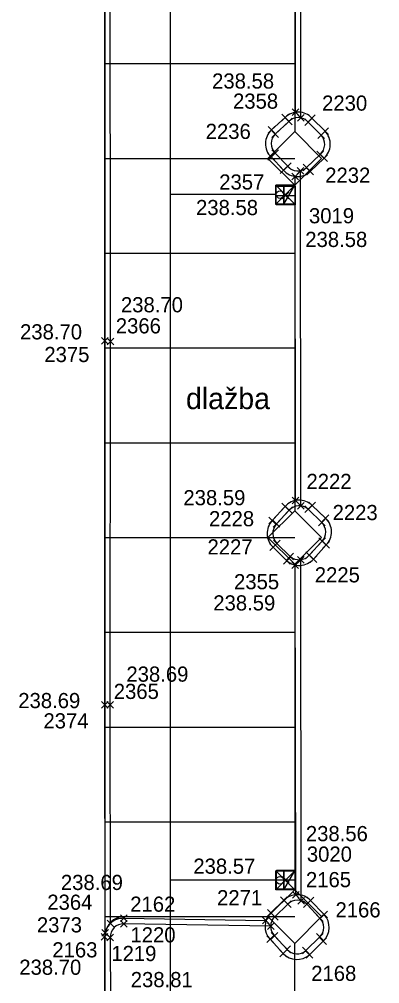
# Model space of a CAD drawing. Extents: x -264222 to -263676, y -1242344 to -1242060.
# Drawn here: x -264127.84 to -264118.33, y -1242272.25 to -1242246.81 of the extents above; entities that cross this region are included whole.
import ezdxf

# ---------------------------------------------------------------- set-up
doc = ezdxf.new("R2010")
doc.units = 0
for name, color, linetype in [('BODY_CISLO', 7, 'Continuous'), ('BODY_SYMBOL', 7, 'Continuous'), ('BODY_VYSKA', 7, 'Continuous'), ('BODY_VYSKY_UV', 7, 'Continuous'), ('KOORDINACNA_SITUACIA_DSP', 7, 'Continuous'), ('POPIS', 7, 'Continuous'), ('PROJEKT_DRS_OBRUBNIKY_KOMUNIKACIE', 7, 'Continuous'), ('PROJEKT_DRS_TDZ_VODOROVNE', 7, 'Continuous'), ('PROJEKT_DRS_UV_STAVBY', 7, 'Continuous'), ('SO_20-3_OBRUBNIKY_DOLNA_HRANA', 7, 'Continuous'), ('SO_20-3_OBRUBNIKY_HORNA_HRANA', 7, 'Continuous'), ('ULICNA_VPUST_POKLOP', 7, 'Continuous')]:
    doc.layers.add(name, color=color, linetype=linetype)

msp = doc.modelspace()

# ---------------------------------------------------------------- linework, layer by layer
at = {"layer": 'BODY_SYMBOL'}
for p, q in [((-264120.638, -1242249.353), (-264120.462, -1242249.177)), ((-264120.462, -1242249.353), (-264120.638, -1242249.177)), ((-264120.912, -1242249.488), (-264120.736, -1242249.312)), ((-264120.736, -1242249.488), (-264120.912, -1242249.312)), ((-264120.813, -1242249.596), (-264120.637, -1242249.42)), ((-264120.637, -1242249.596), (-264120.813, -1242249.42)), ((-264120.493, -1242249.503), (-264120.317, -1242249.327)), ((-264120.317, -1242249.503), (-264120.493, -1242249.327)), ((-264120.302, -1242249.612), (-264120.126, -1242249.436)), ((-264120.126, -1242249.612), (-264120.302, -1242249.436)), ((-264120.203, -1242249.506), (-264120.027, -1242249.33)), ((-264120.027, -1242249.506), (-264120.203, -1242249.33)), ((-264121.27, -1242249.82), (-264121.094, -1242249.644)), ((-264121.094, -1242249.82), (-264121.27, -1242249.644)), ((-264119.858, -1242249.853), (-264119.682, -1242249.677)), ((-264119.682, -1242249.853), (-264119.858, -1242249.677)), ((-264121.17, -1242249.928), (-264120.994, -1242249.752)), ((-264120.994, -1242249.928), (-264121.17, -1242249.752)), ((-264119.961, -1242249.957), (-264119.785, -1242249.781)), ((-264119.785, -1242249.957), (-264119.961, -1242249.781)), ((-264121.282, -1242250.533), (-264121.106, -1242250.357)), ((-264121.106, -1242250.533), (-264121.282, -1242250.357)), ((-264121.174, -1242250.429), (-264120.998, -1242250.253)), ((-264120.998, -1242250.429), (-264121.174, -1242250.253)), ((-264119.987, -1242250.466), (-264119.811, -1242250.29)), ((-264119.811, -1242250.466), (-264119.987, -1242250.29)), ((-264119.884, -1242250.568), (-264119.708, -1242250.392)), ((-264119.708, -1242250.568), (-264119.884, -1242250.392)), ((-264120.952, -1242250.884), (-264120.776, -1242250.708)), ((-264120.776, -1242250.884), (-264120.952, -1242250.708)), ((-264120.843, -1242250.78), (-264120.667, -1242250.604)), ((-264120.667, -1242250.78), (-264120.843, -1242250.604)), ((-264120.508, -1242250.896), (-264120.332, -1242250.72)), ((-264120.332, -1242250.896), (-264120.508, -1242250.72)), ((-264120.346, -1242250.812), (-264120.17, -1242250.636)), ((-264120.17, -1242250.812), (-264120.346, -1242250.636)), ((-264120.249, -1242250.917), (-264120.073, -1242250.741)), ((-264120.073, -1242250.917), (-264120.249, -1242250.741)), ((-264120.648, -1242251.045), (-264120.472, -1242250.869)), ((-264120.472, -1242251.045), (-264120.648, -1242250.869)), ((-264120.898, -1242251.549), (-264120.722, -1242251.373)), ((-264120.722, -1242251.549), (-264120.898, -1242251.373)), ((-264125.663, -1242255.387), (-264125.487, -1242255.211)), ((-264125.487, -1242255.387), (-264125.663, -1242255.211)), ((-264125.519, -1242255.403), (-264125.343, -1242255.227)), ((-264125.343, -1242255.403), (-264125.519, -1242255.227)), ((-264120.909, -1242259.752), (-264120.733, -1242259.576)), ((-264120.733, -1242259.752), (-264120.909, -1242259.576)), ((-264120.636, -1242259.595), (-264120.46, -1242259.419)), ((-264120.46, -1242259.595), (-264120.636, -1242259.419)), ((-264120.493, -1242259.737), (-264120.317, -1242259.561)), ((-264120.317, -1242259.737), (-264120.493, -1242259.561)), ((-264120.304, -1242259.823), (-264120.128, -1242259.647)), ((-264120.128, -1242259.823), (-264120.304, -1242259.647)), ((-264120.195, -1242259.725), (-264120.019, -1242259.549)), ((-264120.019, -1242259.725), (-264120.195, -1242259.549)), ((-264120.801, -1242259.853), (-264120.625, -1242259.677)), ((-264120.625, -1242259.853), (-264120.801, -1242259.677)), ((-264119.842, -1242260.064), (-264119.666, -1242259.888)), ((-264119.666, -1242260.064), (-264119.842, -1242259.888)), ((-264121.25, -1242260.124), (-264121.074, -1242259.948)), ((-264121.074, -1242260.124), (-264121.25, -1242259.948)), ((-264121.135, -1242260.213), (-264120.959, -1242260.037)), ((-264120.959, -1242260.213), (-264121.135, -1242260.037)), ((-264119.946, -1242260.173), (-264119.77, -1242259.997)), ((-264119.77, -1242260.173), (-264119.946, -1242259.997)), ((-264121.227, -1242260.829), (-264121.051, -1242260.653)), ((-264121.051, -1242260.829), (-264121.227, -1242260.653)), ((-264121.126, -1242260.725), (-264120.95, -1242260.549)), ((-264120.95, -1242260.725), (-264121.126, -1242260.549)), ((-264119.935, -1242260.67), (-264119.759, -1242260.494)), ((-264119.759, -1242260.67), (-264119.935, -1242260.494)), ((-264119.824, -1242260.768), (-264119.648, -1242260.592)), ((-264119.648, -1242260.768), (-264119.824, -1242260.592)), ((-264120.773, -1242261.071), (-264120.597, -1242260.895)), ((-264120.597, -1242261.071), (-264120.773, -1242260.895)), ((-264120.272, -1242261.039), (-264120.096, -1242260.863)), ((-264120.096, -1242261.039), (-264120.272, -1242260.863)), ((-264120.864, -1242261.184), (-264120.688, -1242261.008)), ((-264120.688, -1242261.184), (-264120.864, -1242261.008)), ((-264120.643, -1242261.297), (-264120.467, -1242261.121)), ((-264120.467, -1242261.297), (-264120.643, -1242261.121)), ((-264120.499, -1242261.156), (-264120.323, -1242260.98)), ((-264120.323, -1242261.156), (-264120.499, -1242260.98)), ((-264120.165, -1242261.139), (-264119.989, -1242260.963)), ((-264119.989, -1242261.139), (-264120.165, -1242260.963)), ((-264125.666, -1242264.983), (-264125.49, -1242264.807)), ((-264125.49, -1242264.983), (-264125.666, -1242264.807)), ((-264125.525, -1242264.988), (-264125.349, -1242264.812)), ((-264125.349, -1242264.988), (-264125.525, -1242264.812)), ((-264120.89, -1242269.598), (-264120.714, -1242269.422)), ((-264120.714, -1242269.598), (-264120.89, -1242269.422)), ((-264120.625, -1242269.995), (-264120.449, -1242269.819)), ((-264120.449, -1242269.995), (-264120.625, -1242269.819)), ((-264120.942, -1242270.136), (-264120.766, -1242269.96)), ((-264120.766, -1242270.136), (-264120.942, -1242269.96)), ((-264120.842, -1242270.242), (-264120.666, -1242270.066)), ((-264120.666, -1242270.242), (-264120.842, -1242270.066)), ((-264120.487, -1242270.152), (-264120.311, -1242269.976)), ((-264120.311, -1242270.152), (-264120.487, -1242269.976)), ((-264120.337, -1242270.245), (-264120.161, -1242270.069)), ((-264120.161, -1242270.245), (-264120.337, -1242270.069)), ((-264120.24, -1242270.146), (-264120.064, -1242269.97)), ((-264120.064, -1242270.146), (-264120.24, -1242269.97)), ((-264121.288, -1242270.471), (-264121.112, -1242270.295)), ((-264121.112, -1242270.471), (-264121.288, -1242270.295)), ((-264125.517, -1242270.75), (-264125.341, -1242270.574)), ((-264125.341, -1242270.75), (-264125.517, -1242270.574)), ((-264125.165, -1242270.615), (-264124.989, -1242270.439)), ((-264124.989, -1242270.615), (-264125.165, -1242270.439)), ((-264125.164, -1242270.765), (-264124.988, -1242270.589)), ((-264124.988, -1242270.765), (-264125.164, -1242270.589)), ((-264121.415, -1242270.673), (-264121.239, -1242270.497)), ((-264121.239, -1242270.673), (-264121.415, -1242270.497)), ((-264121.184, -1242270.575), (-264121.008, -1242270.399)), ((-264121.008, -1242270.575), (-264121.184, -1242270.399)), ((-264119.991, -1242270.61), (-264119.815, -1242270.434)), ((-264119.815, -1242270.61), (-264119.991, -1242270.434)), ((-264119.88, -1242270.513), (-264119.704, -1242270.337)), ((-264119.704, -1242270.513), (-264119.88, -1242270.337)), ((-264125.661, -1242271.003), (-264125.485, -1242270.827)), ((-264125.485, -1242271.003), (-264125.661, -1242270.827)), ((-264121.291, -1242270.82), (-264121.115, -1242270.644)), ((-264121.115, -1242270.82), (-264121.291, -1242270.644)), ((-264125.673, -1242271.105), (-264125.497, -1242270.929)), ((-264125.497, -1242271.105), (-264125.673, -1242270.929)), ((-264125.523, -1242271.118), (-264125.347, -1242270.942)), ((-264125.347, -1242271.118), (-264125.523, -1242270.942)), ((-264121.304, -1242271.17), (-264121.128, -1242270.994)), ((-264121.128, -1242271.17), (-264121.304, -1242270.994)), ((-264121.193, -1242271.076), (-264121.017, -1242270.9)), ((-264121.017, -1242271.076), (-264121.193, -1242270.9)), ((-264119.992, -1242271.108), (-264119.816, -1242270.932)), ((-264119.816, -1242271.108), (-264119.992, -1242270.932)), ((-264119.903, -1242271.219), (-264119.727, -1242271.043)), ((-264119.727, -1242271.219), (-264119.903, -1242271.043)), ((-264120.857, -1242271.434), (-264120.681, -1242271.258)), ((-264120.681, -1242271.434), (-264120.857, -1242271.258)), ((-264120.36, -1242271.465), (-264120.184, -1242271.289)), ((-264120.184, -1242271.465), (-264120.36, -1242271.289)), ((-264120.966, -1242271.54), (-264120.79, -1242271.364)), ((-264120.79, -1242271.54), (-264120.966, -1242271.364)), ((-264120.264, -1242271.576), (-264120.088, -1242271.4)), ((-264120.088, -1242271.576), (-264120.264, -1242271.4))]:
    msp.add_line(p, q, dxfattribs=at)
at = {"layer": 'KOORDINACNA_SITUACIA_DSP'}
for p, q in [((-264123.854, -1242237.976), (-264123.854, -1242297.736)), ((-264120.568, -1242241.189), (-264120.568, -1242249.774)), ((-264120.857, -1242251.689), (-264120.857, -1242251.189)), ((-264120.857, -1242251.189), (-264120.567, -1242251.189)), ((-264120.857, -1242251.689), (-264120.567, -1242251.189)), ((-264120.857, -1242251.689), (-264120.567, -1242251.189)), ((-264120.567, -1242251.189), (-264120.857, -1242251.189)), ((-264120.857, -1242251.189), (-264120.857, -1242251.689)), ((-264120.568, -1242251.191), (-264120.568, -1242259.775)), ((-264120.567, -1242251.189), (-264120.567, -1242251.689)), ((-264121.057, -1242251.439), (-264123.853, -1242251.439)), ((-264120.567, -1242251.689), (-264120.857, -1242251.689)), ((-264120.568, -1242261.189), (-264120.568, -1242269.774)), ((-264120.857, -1242269.775), (-264120.857, -1242269.275)), ((-264120.857, -1242269.275), (-264120.567, -1242269.275)), ((-264120.857, -1242269.775), (-264120.567, -1242269.275)), ((-264120.857, -1242269.775), (-264120.567, -1242269.275)), ((-264120.567, -1242269.275), (-264120.857, -1242269.275)), ((-264120.857, -1242269.275), (-264120.857, -1242269.775)), ((-264120.567, -1242269.275), (-264120.567, -1242269.775)), ((-264121.058, -1242269.525), (-264123.854, -1242269.525)), ((-264120.567, -1242269.775), (-264120.857, -1242269.775)), ((-264125.068, -1242270.482), (-264121.275, -1242270.482)), ((-264125.568, -1242287.467), (-264125.568, -1242270.982))]:
    msp.add_line(p, q, dxfattribs=at)
for points in [[(-264120.568, -1242249.775), (-264119.861, -1242250.482), (-264120.568, -1242251.189), (-264121.275, -1242250.482)], [(-264120.568, -1242259.775), (-264119.861, -1242260.482), (-264120.568, -1242261.189), (-264121.275, -1242260.482)], [(-264120.568, -1242269.775), (-264119.861, -1242270.482), (-264120.568, -1242271.189), (-264121.275, -1242270.482)]]:
    msp.add_lwpolyline(points, close=True, dxfattribs=at)
msp.add_lwpolyline([(-264120.568, -1242296.035), (-264120.568, -1242271.189), (-264120.568, -1242271.189)], dxfattribs=at)
for centre in [(-264120.957, -1242251.439), (-264120.958, -1242269.525)]:
    msp.add_circle(centre, 0.1, dxfattribs=at)
msp.add_arc((-264125.068, -1242270.982), 0.5, 90, 180, dxfattribs=at)
at = {"layer": 'PROJEKT_DRS_OBRUBNIKY_KOMUNIKACIE'}
for p, q in [((-264125.568, -1242270.982), (-264125.568, -1242191.482)), ((-264120.568, -1242241.189), (-264120.568, -1242249.774)), ((-264120.568, -1242251.191), (-264120.568, -1242259.775)), ((-264120.568, -1242261.189), (-264120.568, -1242269.774)), ((-264125.068, -1242270.482), (-264121.275, -1242270.482)), ((-264125.568, -1242287.467), (-264125.568, -1242270.982)), ((-264120.568, -1242296.035), (-264120.568, -1242271.189))]:
    msp.add_line(p, q, dxfattribs=at)
for points in [[(-264120.568, -1242249.775), (-264119.861, -1242250.482), (-264120.568, -1242251.189), (-264121.275, -1242250.482), (-264120.568, -1242249.775)], [(-264120.568, -1242259.775), (-264119.861, -1242260.482), (-264120.568, -1242261.189), (-264121.275, -1242260.482), (-264120.568, -1242259.775)], [(-264120.568, -1242269.775), (-264119.861, -1242270.482), (-264120.568, -1242271.189), (-264121.275, -1242270.482), (-264120.568, -1242269.775)]]:
    msp.add_lwpolyline(points, dxfattribs=at)
msp.add_arc((-264125.068, -1242270.982), 0.5, 90, 180, dxfattribs=at)
at = {"layer": 'PROJEKT_DRS_TDZ_VODOROVNE'}
for p, q in [((-264125.568, -1242247.982), (-264120.568, -1242247.982)), ((-264125.568, -1242250.482), (-264120.568, -1242250.482)), ((-264125.568, -1242252.982), (-264120.568, -1242252.982)), ((-264125.568, -1242255.482), (-264120.568, -1242255.482)), ((-264125.568, -1242257.982), (-264120.568, -1242257.982)), ((-264125.568, -1242260.482), (-264120.568, -1242260.482)), ((-264125.568, -1242262.982), (-264120.568, -1242262.982)), ((-264125.568, -1242265.482), (-264120.568, -1242265.482)), ((-264125.568, -1242267.982), (-264120.568, -1242267.982)), ((-264125.568, -1242270.482), (-264120.568, -1242270.482))]:
    msp.add_line(p, q, dxfattribs=at)
at = {"layer": 'PROJEKT_DRS_UV_STAVBY'}
for points in [[(-264121.067, -1242251.689), (-264121.067, -1242251.189), (-264120.567, -1242251.189), (-264120.567, -1242251.689), (-264121.067, -1242251.689), (-264120.567, -1242251.189), (-264121.067, -1242251.189), (-264120.567, -1242251.689)], [(-264121.067, -1242269.775), (-264121.067, -1242269.275), (-264120.567, -1242269.275), (-264120.567, -1242269.775), (-264121.067, -1242269.775), (-264120.567, -1242269.275), (-264121.067, -1242269.275), (-264120.567, -1242269.775)]]:
    msp.add_lwpolyline(points, dxfattribs=at)
at = {"layer": 'SO_20-3_OBRUBNIKY_DOLNA_HRANA'}
for p, q in [((-264120.55, -1242249.265), (-264120.554, -1242241.349)), ((-264121.182, -1242249.732), (-264120.824, -1242249.4)), ((-264120.115, -1242249.418), (-264119.77, -1242249.765)), ((-264120.864, -1242250.796), (-264121.194, -1242250.445)), ((-264119.796, -1242250.48), (-264120.161, -1242250.829)), ((-264120.548, -1242259.507), (-264120.56, -1242250.957)), ((-264120.107, -1242259.637), (-264119.754, -1242259.976)), ((-264121.162, -1242260.036), (-264120.821, -1242259.664)), ((-264120.776, -1242261.096), (-264121.139, -1242260.741)), ((-264119.736, -1242260.68), (-264120.077, -1242261.051)), ((-264120.537, -1242269.907), (-264120.555, -1242261.209)), ((-264121.2, -1242270.383), (-264120.854, -1242270.048)), ((-264120.152, -1242270.058), (-264119.792, -1242270.425)), ((-264125.077, -1242270.527), (-264121.327, -1242270.585)), ((-264120.878, -1242271.452), (-264121.216, -1242271.082)), ((-264119.815, -1242271.131), (-264120.176, -1242271.488))]:
    msp.add_line(p, q, dxfattribs=at)
for points in [[(-264125.573, -1242270.915), (-264125.578, -1242264.895), (-264125.575, -1242255.299), (-264125.581, -1242244.324), (-264125.582, -1242233.844), (-264125.584, -1242219.84), (-264125.593, -1242209.81), (-264125.59, -1242197.798), (-264125.59, -1242191.484)], [(-264125.429, -1242270.662), (-264125.437, -1242264.9), (-264125.431, -1242255.315), (-264125.435, -1242244.34), (-264125.439, -1242233.845), (-264125.44, -1242219.841), (-264125.448, -1242209.814), (-264125.447, -1242197.797), (-264125.435, -1242191.484)], [(-264125.585, -1242271.017), (-264125.561, -1242281.034), (-264125.551, -1242287.051)]]:
    msp.add_lwpolyline(points, dxfattribs=at)
for centre, major_axis, ratio, start_param, end_param in [((-264120.478, -1242249.757), (-0.496, 0.013), 0.999976, 3.917165, 5.507613), ((-264120.853, -1242250.094), (-0.008, -0.489), 0.99979, 3.896384, 5.528394), ((-264120.125, -1242250.11), (-0.05, 0.493), 0.999948, 3.767556, 5.382488), ((-264120.496, -1242250.47), (0.231, 0.434), 0.99998, 2.785165, 4.380766), ((-264120.451, -1242259.991), (-0.446, 0.213), 0.999982, 4.387078, 6.003781), ((-264120.802, -1242260.377), (-0.169, -0.466), 0.999971, 4.300812, 5.883738), ((-264120.094, -1242260.337), (-0.243, 0.432), 0.999885, 3.436393, 5.015373), ((-264120.449, -1242260.728), (0.434, 0.234), 0.999977, 3.491254, 5.073033), ((-264120.508, -1242270.4), (-0.425, 0.251), 0.999963, 4.439778, 6.021899), ((-264125.088, -1242271.024), (-0.497, -0.011), 0.999893, 4.66727, 6.246237), ((-264120.856, -1242270.741), (0.329, -0.372), 0.999965, 3.183838, 4.746565), ((-264120.161, -1242270.766), (-0.26, 0.43), 0.999916, 3.356902, 4.915899), ((-264120.508, -1242271.108), (0.496, -0.095), 0.999785, 4.080051, 5.620303)]:
    msp.add_ellipse(centre, major_axis=major_axis, ratio=ratio, start_param=start_param, end_param=end_param, dxfattribs=at)
at = {"layer": 'SO_20-3_OBRUBNIKY_HORNA_HRANA'}
for p, q in [((-264120.405, -1242249.415), (-264120.41, -1242241.185)), ((-264121.082, -1242249.84), (-264120.725, -1242249.508)), ((-264120.214, -1242249.524), (-264119.873, -1242249.869)), ((-264120.755, -1242250.692), (-264121.086, -1242250.341)), ((-264119.899, -1242250.378), (-264120.258, -1242250.724)), ((-264120.405, -1242259.649), (-264120.42, -1242250.808)), ((-264121.047, -1242260.125), (-264120.713, -1242259.765)), ((-264120.216, -1242259.735), (-264119.858, -1242260.085)), ((-264120.685, -1242260.983), (-264121.038, -1242260.637)), ((-264119.847, -1242260.582), (-264120.184, -1242260.951)), ((-264120.399, -1242270.064), (-264120.411, -1242261.068)), ((-264120.754, -1242270.154), (-264121.096, -1242270.487)), ((-264119.903, -1242270.522), (-264120.249, -1242270.157)), ((-264121.203, -1242270.732), (-264125.076, -1242270.677)), ((-264125.435, -1242271.03), (-264125.41, -1242287.033)), ((-264121.105, -1242270.988), (-264120.769, -1242271.346)), ((-264120.272, -1242271.377), (-264119.904, -1242271.02))]:
    msp.add_line(p, q, dxfattribs=at)
for centre, major_axis, ratio, start_param, end_param in [((-264120.477, -1242249.764), (-0.351, 0.062), 0.999629, 4.05561, 5.657259), ((-264120.842, -1242250.092), (-0.081, -0.339), 0.999363, 4.135616, 5.740237), ((-264120.132, -1242250.111), (0.001, 0.354), 0.999133, 3.862601, 5.467869), ((-264120.491, -1242250.471), (0.337, 0.069), 0.999736, 3.638527, 5.255914), ((-264120.45, -1242259.996), (-0.35, 0.016), 0.999265, 4.028104, 5.60664), ((-264120.788, -1242260.377), (-0.024, -0.36), 0.999723, 4.006897, 5.58404), ((-264120.099, -1242260.339), (-0.008, 0.35), 0.99958, 3.923297, 5.501481), ((-264120.45, -1242260.713), (0.344, 0.097), 0.99713, 3.722556, 5.278139), ((-264120.503, -1242270.4), (-0.32, 0.145), 0.999953, 4.331761, 5.933159), ((-264120.846, -1242270.742), (-0.042, 0.355), 0.999563, 0.658118, 2.212755), ((-264120.16, -1242270.77), (0.045, -0.355), 0.9995, 0.673162, 2.21368), ((-264125.096, -1242271.016), (-0.126, -0.315), 0.999014, 3.461931, 5.134146), ((-264120.505, -1242271.12), (-0.347, -0.014), 0.99922, 0.669975, 2.267851)]:
    msp.add_ellipse(centre, major_axis=major_axis, ratio=ratio, start_param=start_param, end_param=end_param, dxfattribs=at)
at = {"layer": 'ULICNA_VPUST_POKLOP'}
for p, q in [((-264120.81, -1242251.461), (-264120.81, -1242251.461)), ((-264120.802, -1242269.51), (-264120.802, -1242269.51))]:
    msp.add_line(p, q, dxfattribs=at)
for points in [[(-264121.06, -1242251.461), (-264121.06, -1242251.211), (-264120.56, -1242251.211), (-264120.56, -1242251.711), (-264121.06, -1242251.711), (-264121.06, -1242251.461), (-264120.56, -1242251.461)], [(-264121.052, -1242269.51), (-264121.052, -1242269.26), (-264120.552, -1242269.26), (-264120.552, -1242269.76), (-264121.052, -1242269.76), (-264121.052, -1242269.51), (-264120.552, -1242269.51)]]:
    msp.add_lwpolyline(points, dxfattribs=at)

# ---------------------------------------------------------------- texts
at = {"layer": 'BODY_CISLO'}
for s, p in [('2358', (-264122.197, -1242249.172)), ('2230', (-264119.847, -1242249.224)), ('2236', (-264122.918, -1242249.97)), ('2232', (-264119.765, -1242251.126)), ('2357', (-264122.561, -1242251.305)), ('3019', (-264120.193, -1242252.195)), ('2366', (-264125.289, -1242255.099)), ('2375', (-264127.175, -1242255.855)), ('2222', (-264120.259, -1242259.203)), ('2223', (-264119.57, -1242260.024)), ('2228', (-264122.83, -1242260.186)), ('2227', (-264122.87, -1242260.931)), ('2225', (-264120.04, -1242261.667)), ('2355', (-264122.17, -1242261.848)), ('2365', (-264125.343, -1242264.742)), ('2374', (-264127.199, -1242265.519)), ('3020', (-264120.249, -1242269.034)), ('2165', (-264120.273, -1242269.707)), ('2271', (-264122.617, -1242270.184)), ('2364', (-264127.097, -1242270.303)), ('2162', (-264124.909, -1242270.354)), ('2166', (-264119.493, -1242270.504)), ('2373', (-264127.372, -1242270.9)), ('1220', (-264124.903, -1242271.164)), ('2163', (-264126.964, -1242271.559)), ('1219', (-264125.408, -1242271.656)), ('2168', (-264120.134, -1242272.18))]:
    msp.add_text(s, height=0.4, dxfattribs=at).set_placement(p)
at = {"layer": 'BODY_VYSKA'}
for s, p in [('238.58', (-264122.749, -1242248.641)), ('238.58', (-264123.173, -1242251.979)), ('238.70', (-264125.154, -1242254.543)), ('238.70', (-264127.816, -1242255.257)), ('238.59', (-264123.506, -1242259.632)), ('238.59', (-264122.718, -1242262.408)), ('238.69', (-264125.01, -1242264.286)), ('238.69', (-264127.863, -1242264.984)), ('238.57', (-264123.244, -1242269.352)), ('238.69', (-264126.738, -1242269.781)), ('238.70', (-264127.836, -1242272.018)), ('238.81', (-264124.895, -1242272.344))]:
    msp.add_text(s, height=0.4, dxfattribs=at).set_placement(p)
at = {"layer": 'BODY_VYSKY_UV'}
for s, p in [('238.58', (-264120.291, -1242252.82)), ('238.56', (-264120.275, -1242268.493))]:
    msp.add_text(s, height=0.4, dxfattribs=at).set_placement(p)
at = {"layer": 'POPIS'}
msp.add_text('dlažba', height=0.5625, rotation=360, dxfattribs=at).set_placement((-264123.438, -1242257.097))

doc.saveas('drawing.dxf')
